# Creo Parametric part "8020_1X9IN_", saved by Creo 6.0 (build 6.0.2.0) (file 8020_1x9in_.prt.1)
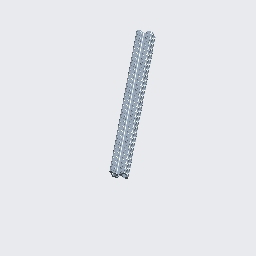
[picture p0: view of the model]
Units: Inch lbm Second (Pro/E Default); INCH, POUND, SECS

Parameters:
  DESC1 = "Aluminum"
  DESC2 = "T-Slotted Framing"
  DESC3 = "© 2015 McMaster-Carr Supply Company"
  CAD_SYSTEM = "SOLIDWORKS_PART"
  DEX_MASTER = "47065T411_ALUMINUM T-SLOTTED FRAMING EXTRUSION"
  MODEL_VERSION = "N/A"
  MODEL_DATE = "07/30/2021 11:22:22"
  TIM_STATUS = "Up-To-Date"
  REF_LINK = "C:\Users\Nathan\Downloads\47065T411_ALUMINUM T-SLOTTED FRAMING EXTRUSION.SLDPRT"
  NATIVE_NAME = "47065T411_ALUMINUM T-SLOTTED FRAMING EXTRUSION"

Created from: 47065T411_ALUMINUM T-SLOTTED FRAMING EXTRUSION.PRT

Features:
  1. imported feature "Solidworks id 1"
  2. datum plane "DTM1"
  3. datum plane "DEFAULT_1"
  4. sketch "Sketch 1"
  5. extruded cut "Extrude 1"
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
Other named items: FRONT PLANE, TOP PLANE, RIGHT PLANE

Layers: SHELL

Surfaces: 54 cylinder, 46 plane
